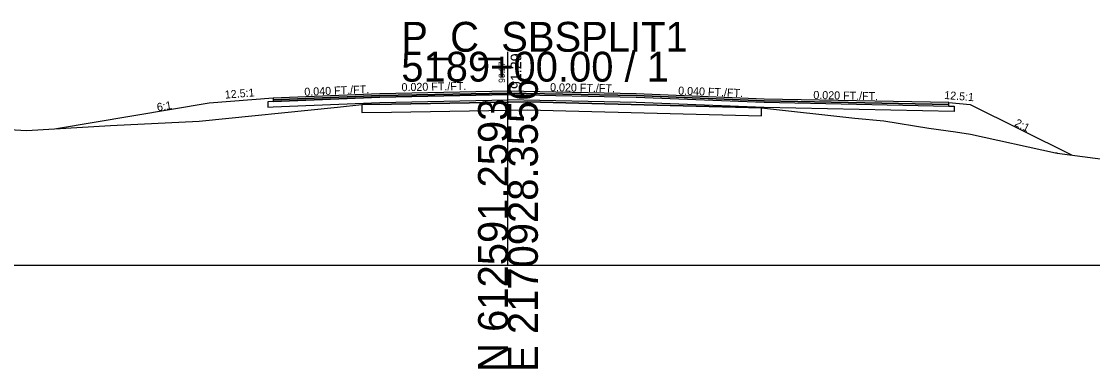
# Model space of a CAD drawing. Extents: x -26 to 1303, y -3010 to 12023.
# Drawn here: x 104.4 to 204.8, y 8990.3 to 9022.8 of the extents above; entities that cross this region are included whole.
import ezdxf

# ---------------------------------------------------------------- set-up
doc = ezdxf.new("R2010")
doc.units = 0
for name, color, linetype in [('RD_GPK_XS_Cell', 7, 'Continuous'), ('RD_XS_Base', 7, 'Continuous'), ('RD_XS_ExGround', 7, 'Continuous'), ('RD_XS_ExPaveRet', 7, 'Continuous'), ('RD_XS_Greenside', 7, 'Continuous'), ('RD_XS_Pave', 7, 'Continuous'), ('RD_XS_PaveOvlay_CP', 7, 'Continuous'), ('RD_XS_TieSlope', 7, 'Continuous'), ('RD_XS_TX_Elev_EX', 7, 'Continuous'), ('RD_XS_TX_Elev_PR', 7, 'Continuous'), ('RD_XS_TX_ShdSlope', 7, 'Continuous'), ('RD_XS_TX_Slope', 7, 'Continuous')]:
    doc.layers.add(name, color=color, linetype=linetype)

msp = doc.modelspace()

# ---------------------------------------------------------------- linework, layer by layer
at = {"layer": 'RD_GPK_XS_Cell'}
for p, q in [((150, 9000), (150, 9020)), ((0, 9000), (150, 9000)), ((150, 9000), (300, 9000))]:
    msp.add_line(p, q, dxfattribs=at)
at = {"layer": 'RD_XS_Base'}
for p, q in [((150, 9015.48), (150, 9016.13)), ((150, 9016.13), (150, 9016.13)), ((150, 9016.13), (150, 9016.13)), ((150, 9016.13), (150, 9015.98)), ((128, 9015.34), (127.5, 9015.32)), ((127.5, 9015.32), (127.5, 9015.32)), ((127.5, 9015.32), (127.5, 9014.82)), ((138, 9015.74), (128, 9015.34)), ((128, 9015.34), (128, 9015.34)), ((128, 9014.84), (138, 9015.24)), ((136, 9015.66), (136, 9015.66)), ((136, 9015.16), (136, 9015.16)), ((150, 9015.98), (138, 9015.74)), ((138, 9015.24), (150, 9015.48)), ((150, 9015.98), (150, 9015.98)), ((150, 9015.98), (162, 9015.74)), ((150, 9015.98), (150, 9015.98)), ((150, 9015.48), (150, 9015.98)), ((150, 9015.98), (150, 9015.98)), ((150, 9015.98), (150, 9015.98)), ((162, 9015.24), (150, 9015.48)), ((150, 9015.48), (150, 9015.48)), ((150, 9015.48), (150, 9015.48)), ((162, 9015.74), (162, 9015.74)), ((162, 9015.74), (174, 9015.26)), ((174, 9014.76), (162, 9015.24)), ((162, 9015.24), (162, 9015.24)), ((174, 9015.26), (174, 9015.26)), ((174, 9015.26), (191.32, 9014.91)), ((127.5, 9014.82), (128, 9014.84)), ((128, 9014.84), (128, 9014.84)), ((191.82, 9014.4), (174, 9014.76)), ((174, 9014.76), (174, 9014.76)), ((191.32, 9014.91), (191.32, 9014.91)), ((191.32, 9014.91), (191.82, 9014.9)), ((191.82, 9014.9), (191.82, 9014.9)), ((191.82, 9014.9), (191.82, 9014.4))]:
    msp.add_line(p, q, dxfattribs=at)
at = {"layer": 'RD_XS_ExGround'}
msp.add_lwpolyline([(95.84, 9013.16), (104.88, 9012.63), (112.74, 9013.08), (121.07, 9013.49), (134.01, 9014.82), (136.31, 9015.06), (139.07, 9015.1), (151.87, 9015.3), (155.43, 9015.21), (173.75, 9014.74), (182.52, 9013.79), (185.21, 9013.53), (189.44, 9012.85), (191.94, 9012.49), (193.33, 9012.26), (201.31, 9010.54), (201.42, 9010.52), (201.48, 9010.51), (208.58, 9009.56)], dxfattribs=at)
at = {"layer": 'RD_XS_ExPaveRet'}
for points in [[(173.75, 9014.74), (155.43, 9015.21), (155.43, 9015.21), (151.87, 9015.3), (151.87, 9015.3), (139.07, 9015.1), (139.07, 9015.1), (136.31, 9015.06), (136.31, 9015.06), (136.31, 9014.31), (139.07, 9014.35), (139.07, 9014.35), (151.87, 9014.55), (151.87, 9014.55), (155.43, 9014.46), (155.43, 9014.46), (173.75, 9013.99), (173.75, 9013.99), (173.75, 9013.99), (173.75, 9014.74), (173.75, 9014.74)], [(173.75, 9014.74), (155.43, 9015.21), (151.87, 9015.3), (139.07, 9015.1), (136.31, 9015.06), (136.31, 9014.31), (139.07, 9014.35), (151.87, 9014.55), (155.43, 9014.46), (173.75, 9013.99), (173.75, 9014.74)]]:
    msp.add_lwpolyline(points, dxfattribs=at)
at = {"layer": 'RD_XS_Greenside'}
for p, q in [((122, 9015.17), (107.69, 9012.79)), ((193.32, 9015.07), (193.32, 9015.07)), ((193.32, 9015.07), (202.8, 9010.33))]:
    msp.add_line(p, q, dxfattribs=at)
at = {"layer": 'RD_XS_Pave'}
for p, q in [((150, 9016.29), (138, 9016.05)), ((150, 9016.13), (138, 9015.89)), ((138, 9015.89), (150, 9016.13)), ((162, 9016.05), (150, 9016.29)), ((150, 9016.29), (150, 9016.29)), ((150, 9016.29), (150, 9016.29)), ((150, 9015.98), (150, 9016.13)), ((150, 9016.13), (150, 9016.13)), ((150, 9016.13), (150, 9016.13)), ((150, 9016.13), (150, 9016.13)), ((150, 9016.13), (150, 9016.13)), ((150, 9016.13), (162, 9015.89)), ((162, 9015.89), (150, 9016.13)), ((150, 9016.13), (150, 9016.13)), ((150, 9016.13), (150, 9016.13)), ((150, 9016.13), (150, 9016.13)), ((150, 9016.13), (150, 9015.98)), ((138, 9016.05), (128, 9015.65)), ((138, 9015.89), (128, 9015.49)), ((128, 9015.49), (138, 9015.89)), ((128, 9015.34), (138, 9015.74)), ((128, 9015.65), (128, 9015.65)), ((128, 9015.65), (128, 9015.49)), ((128, 9015.49), (128, 9015.49)), ((128, 9015.49), (128, 9015.34)), ((136, 9015.97), (136, 9015.97)), ((136, 9015.81), (136, 9015.81)), ((136, 9015.81), (136, 9015.81)), ((136, 9015.66), (136, 9015.66)), ((138, 9015.74), (150, 9015.98)), ((150, 9015.98), (150, 9015.98)), ((150, 9015.98), (150, 9015.98)), ((150, 9015.98), (150, 9015.98)), ((150, 9015.98), (162, 9015.74)), ((174, 9015.57), (162, 9016.05)), ((162, 9016.05), (162, 9016.05)), ((162, 9015.89), (162, 9015.89)), ((162, 9015.89), (174, 9015.41)), ((174, 9015.41), (162, 9015.89)), ((162, 9015.89), (162, 9015.89)), ((162, 9015.74), (162, 9015.74)), ((162, 9015.74), (174, 9015.26)), ((191.32, 9015.23), (174, 9015.57)), ((174, 9015.57), (174, 9015.57)), ((174, 9015.41), (174, 9015.41)), ((174, 9015.41), (191.32, 9015.07)), ((191.32, 9015.07), (174, 9015.41)), ((174, 9015.41), (174, 9015.41)), ((174, 9015.26), (191.32, 9014.91)), ((174, 9015.26), (174, 9015.26)), ((191.32, 9015.07), (191.32, 9015.23)), ((191.32, 9015.23), (191.32, 9015.23)), ((191.32, 9014.91), (191.32, 9015.07)), ((191.32, 9015.07), (191.32, 9015.07))]:
    msp.add_line(p, q, dxfattribs=at)
at = {"layer": 'RD_XS_PaveOvlay_CP'}
for p, q in [((150, 9016.29), (138, 9016.05)), ((162, 9016.05), (150, 9016.29)), ((150, 9016.29), (150, 9016.29)), ((150, 9016.29), (150, 9016.29)), ((138, 9016.05), (128, 9015.65)), ((136, 9015.97), (136, 9015.97)), ((174, 9015.57), (162, 9016.05)), ((162, 9016.05), (162, 9016.05)), ((191.32, 9015.23), (174, 9015.57)), ((174, 9015.57), (174, 9015.57))]:
    msp.add_line(p, q, dxfattribs=at)
at = {"layer": 'RD_XS_TieSlope'}
for p, q in [((128, 9015.65), (122, 9015.17)), ((191.32, 9015.23), (193.32, 9015.07))]:
    msp.add_line(p, q, dxfattribs=at)

# ---------------------------------------------------------------- texts
at = {"layer": 'RD_GPK_XS_Cell'}
for s, p in [('P_C_SBSPLIT1', (140, 9020)), ('5189+00.00 / 1', (140, 9017.2))]:
    msp.add_text(s, height=2.8, dxfattribs=at).set_placement(p)
for s, p in [('E 2170928.3556', (152.8, 8990)), ('N 612591.2593', (150, 8990))]:
    msp.add_text(s, height=2.8, rotation=90, dxfattribs=at).set_placement(p)
at = {"layer": 'RD_XS_TX_Elev_EX'}
msp.add_text('90.27', height=0.6, rotation=90, dxfattribs=at).set_placement((149.72, 9017.08))
at = {"layer": 'RD_XS_TX_Elev_PR'}
msp.add_text('91.29', height=1, rotation=90, dxfattribs=at).set_placement((151.25, 9016.5))
at = {"layer": 'RD_XS_TX_ShdSlope'}
for rotation, p in [(4.5739, (123.49, 9015.6)), (355.4261, (190.86, 9015.58))]:
    msp.add_text('12.5:1', height=0.75, rotation=rotation, dxfattribs=at).set_placement(p)
at = {"layer": 'RD_XS_TX_Slope'}
for s, rotation, p in [('0.020 FT./FT.', 1.1458, (140.03, 9016.3)), ('0.040 FT./FT.', 2.2906, (130.93, 9015.87)), ('0.020 FT./FT.', 358.8542, (153.94, 9016.31)), ('0.040 FT./FT.', 357.7094, (165.94, 9015.99)), ('0.020 FT./FT.', 358.8542, (178.61, 9015.58)), ('6:1', 9.4623, (117.16, 9014.42)), ('2:1', 333.4349, (197.41, 9013.09))]:
    msp.add_text(s, height=0.75, rotation=rotation, dxfattribs=at).set_placement(p)

doc.saveas('drawing.dxf')
